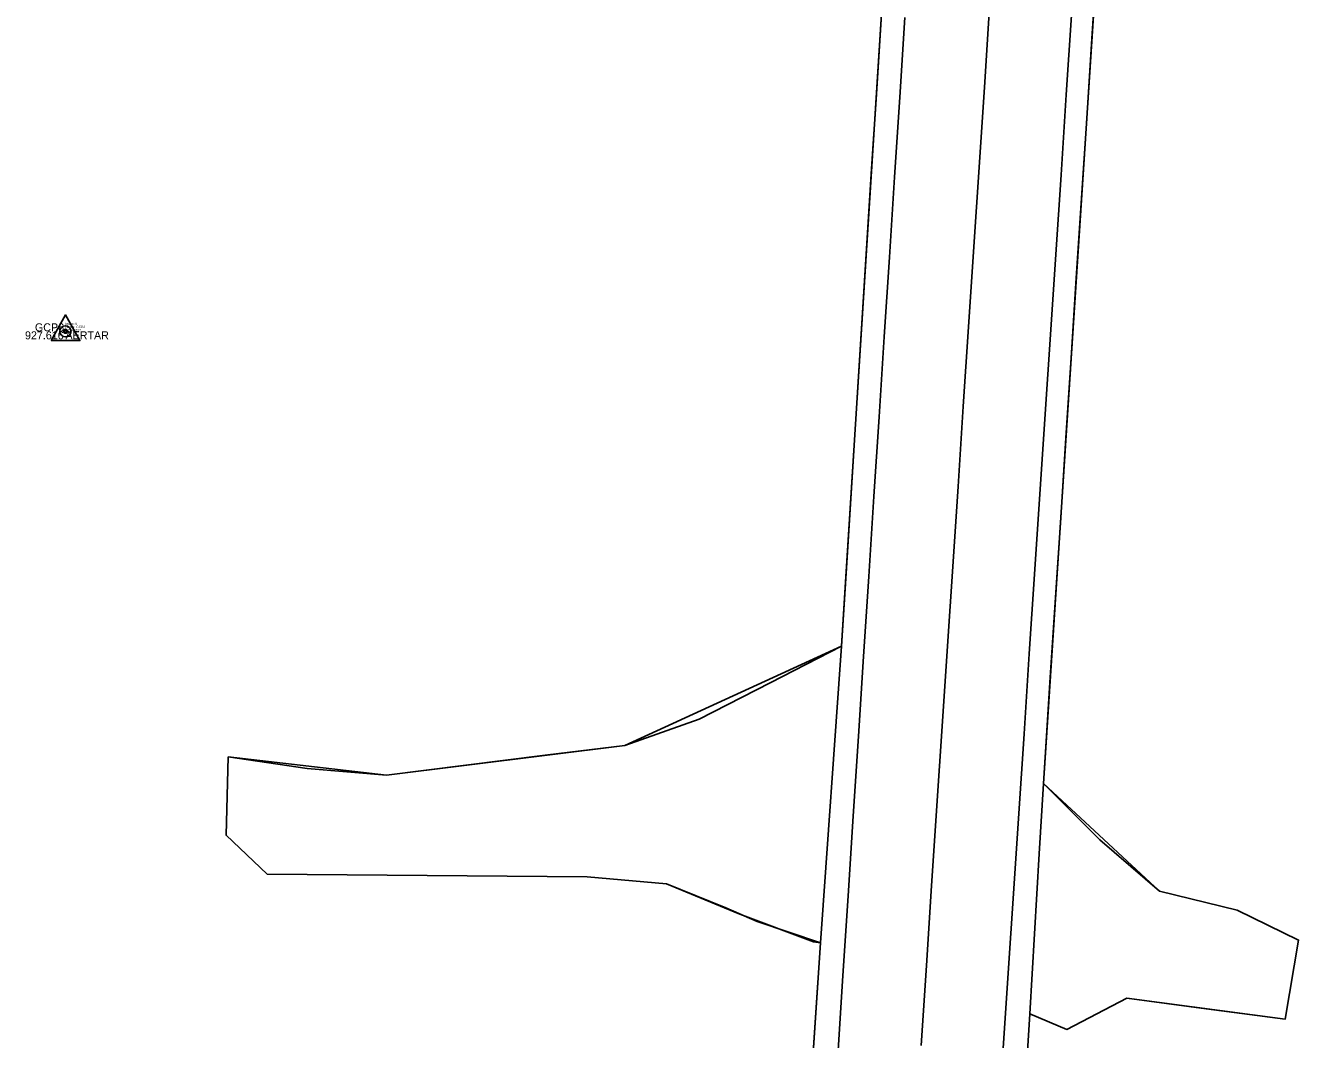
# Model space of a CAD drawing. Extents: x 1988835 to 1989144, y 657973 to 659339.
# Drawn here: x 1988888.5 to 1989047.6, y 658833.1 to 658959.8 of the extents above; entities that cross this region are included whole.
import ezdxf

# ---------------------------------------------------------------- set-up
doc = ezdxf.new("R2010")
doc.units = 0
for name, color, linetype in [('DT_X_Terrain_Boundary', 7, 'Continuous'), ('PM_X_CL_Pass_Proh_Rt', 7, 'Continuous'), ('PV_X_Driveway', 7, 'Continuous'), ('PV_X_EOP', 7, 'Continuous'), ('PV_X_Shoulder_Aggregate', 7, 'Continuous'), ('SV_X_Text_Comment', 7, 'Continuous'), ('SV_X_Text_Elevation', 7, 'Continuous'), ('UT_X_Telecom', 7, 'Continuous'), ('UT_X_Telecom_Cells', 7, 'Continuous')]:
    doc.layers.add(name, color=color, linetype=linetype)

msp = doc.modelspace()

# ---------------------------------------------------------------- linework, layer by layer
at = {"layer": 'DT_X_Terrain_Boundary'}
for points in [[(1989010.62, 659200.77), (1988990.83, 658888.33), (1988990.45, 658882.3), (1988963.36, 658869.89), (1988933.59, 658866.18), (1988913.8, 658868.45), (1988913.53, 658858.66), (1988918.67, 658853.8), (1988958.67, 658853.46), (1988968.57, 658852.58), (1988976.02, 658849.6), (1988979.91, 658847.89), (1988987.83, 658845.23), (1988984.81, 658799.59)], [(1989011.65, 658798.86), (1989014.02, 658836.36), (1989018.64, 658834.4), (1989026.13, 658838.31), (1989045.93, 658835.69), (1989047.59, 658845.55), (1989039.93, 658849.29), (1989030.22, 658851.68), (1989015.7, 658865.14), (1989037.37, 659197.71)]]:
    msp.add_lwpolyline(points, dxfattribs=at)
at = {"layer": 'PM_X_CL_Pass_Proh_Rt'}
msp.add_lwpolyline([(1989000.41, 658832.39), (1989001.07, 658842.37), (1989001.73, 658852.35), (1989002.39, 658862.33), (1989003.05, 658872.3), (1989003.71, 658882.28), (1989004.37, 658892.26), (1989005.03, 658902.24), (1989005.69, 658912.22), (1989006.35, 658922.2), (1989007.01, 658932.17), (1989007.66, 658942.15), (1989008.32, 658952.13), (1989008.98, 658962.11)], dxfattribs=at)
at = {"layer": 'PV_X_Driveway'}
msp.add_line((1988990.45, 658882.3), (1988987.83, 658845.23), dxfattribs=at)
msp.add_lwpolyline([(1988990.45, 658882.3), (1988981.56, 658877.72), (1988972.66, 658873.15), (1988963.36, 658869.89), (1988953.44, 658868.65), (1988943.52, 658867.42), (1988933.59, 658866.18), (1988923.69, 658867.01), (1988913.8, 658868.45), (1988913.53, 658858.66), (1988918.67, 658853.8), (1988928.67, 658853.72), (1988938.67, 658853.63), (1988948.67, 658853.55), (1988958.67, 658853.46), (1988968.57, 658852.58), (1988977.74, 658848.79), (1988986.96, 658845.34), (1988987.83, 658845.23)], dxfattribs=at)
msp.add_lwpolyline([(1989015.7, 658865.14), (1989022.76, 658858.07), (1989030.22, 658851.68), (1989039.93, 658849.29), (1989047.59, 658845.55), (1989045.93, 658835.69), (1989036.04, 658836.98), (1989026.13, 658838.31), (1989018.64, 658834.4), (1989014.02, 658836.36), (1989014.6, 658846.35), (1989015.18, 658856.33)], close=True, dxfattribs=at)
at = {"layer": 'PV_X_EOP'}
for points in [[(1988998.38, 658960.85), (1988997.74, 658950.87), (1988997.09, 658940.89), (1988996.45, 658930.91), (1988995.8, 658920.93), (1988995.16, 658910.95), (1988994.51, 658900.97), (1988993.87, 658890.99), (1988993.22, 658881.01), (1988992.57, 658871.04), (1988991.93, 658861.06), (1988991.28, 658851.08), (1988990.64, 658841.1), (1988989.99, 658831.12)], [(1989010.63, 658831.43), (1989011.29, 658841.41), (1989011.96, 658851.39), (1989012.62, 658861.37), (1989013.28, 658871.35), (1989013.94, 658881.33), (1989014.6, 658891.3), (1989015.26, 658901.28), (1989015.92, 658911.26), (1989016.58, 658921.24), (1989017.24, 658931.22), (1989017.9, 658941.19), (1989018.56, 658951.17), (1989019.22, 658961.15)]]:
    msp.add_lwpolyline(points, dxfattribs=at)
at = {"layer": 'PV_X_Shoulder_Aggregate'}
for points in [[(1989003.67, 659090.99), (1989003.03, 659081.01), (1989002.4, 659071.03), (1989001.77, 659061.05), (1989001.14, 659051.07), (1989000.51, 659041.09), (1988999.87, 659031.11), (1988999.24, 659021.13), (1988998.61, 659011.15), (1988997.98, 659001.17), (1988997.35, 658991.19), (1988996.71, 658981.21), (1988996.08, 658971.23), (1988995.45, 658961.25), (1988994.82, 658951.27), (1988994.19, 658941.29), (1988993.55, 658931.31), (1988992.92, 658921.33), (1988992.29, 658911.35), (1988991.66, 658901.37), (1988991.03, 658891.39), (1988990.45, 658882.3)], [(1989030.22, 659087.94), (1989029.57, 659077.96), (1989028.91, 659067.98), (1989028.26, 659058), (1989027.61, 659048.02), (1989026.96, 659038.04), (1989026.31, 659028.07), (1989025.66, 659018.09), (1989025.01, 659008.11), (1989024.36, 658998.13), (1989023.71, 658988.15), (1989023.06, 658978.17), (1989022.41, 658968.19), (1989021.76, 658958.21), (1989021.11, 658948.24), (1989020.46, 658938.26), (1989019.81, 658928.28), (1989019.16, 658918.3), (1989018.51, 658908.32), (1989017.86, 658898.34), (1989017.21, 658888.36), (1989016.56, 658878.38), (1989015.91, 658868.4), (1989015.7, 658865.14)], [(1988987.83, 658845.23), (1988987.17, 658835.25), (1988986.51, 658825.27)]]:
    msp.add_lwpolyline(points, dxfattribs=at)
at = {"layer": 'SV_X_Text_Elevation'}
msp.add_line((1988893.46, 658921.63), (1988893.46, 658921.63), dxfattribs=at)
msp.add_lwpolyline([(1988891.66, 658920.47), (1988895.26, 658920.47), (1988893.46, 658923.69)], close=True, dxfattribs=at)
for radius in [0.7, 0.16]:
    msp.add_circle((1988893.46, 658921.63), radius, dxfattribs=at)
at = {"layer": 'UT_X_Telecom'}
msp.add_line((1988893.46, 658921.63), (1988893.46, 658921.63), dxfattribs=at)
msp.add_circle((1988893.46, 658921.63), 0.25, dxfattribs=at)

# ---------------------------------------------------------------- texts
at = {"layer": 'SV_X_Text_Comment'}
msp.add_text('GCP6', height=1, dxfattribs=at).set_placement((1988889.64, 658921.63))
at = {"layer": 'UT_X_Telecom'}
for s, height, p in [('ΔZ: -0.227', 0.3, (1988893.46, 658921.63)), ('Name: GCP6', 0.3, (1988893.46, 658922.03)), ('Index: 6', 0.3, (1988893.46, 658922.43)), ('AERTAR', 1, (1988893.46, 658920.63))]:
    msp.add_text(s, height=height, dxfattribs=at).set_placement(p)
at = {"layer": 'UT_X_Telecom_Cells'}
msp.add_text('927.616', height=1, dxfattribs=at).set_placement((1988888.4, 658920.63))

doc.saveas('drawing.dxf')
